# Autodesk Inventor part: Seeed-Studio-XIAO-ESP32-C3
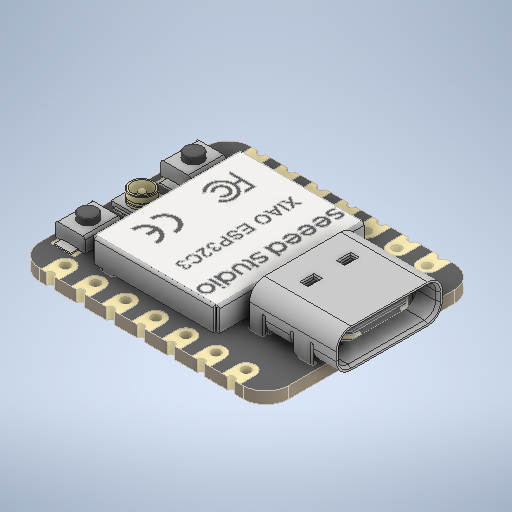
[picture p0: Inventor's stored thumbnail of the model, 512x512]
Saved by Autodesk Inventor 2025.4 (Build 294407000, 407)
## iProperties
Created: 2025-02
Part Number: Seeed-Studio-XIAO-ESP32-C3
Material: Generic
Document SubType Name: Modeling
Designer: Marcio Valenzuela
Density: 1 g/cm^3
Appearance: Default
Sending System: Autodesk Translation Framework v13.20.0.188
Preprocessor: ST-DEVELOPER v20
Title: Seeed-Studio-XIAO-ESP32-C3.step
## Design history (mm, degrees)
feature "BOSS-EXTRUDE14_8__1:1" [Body]
feature "BOSS-EXTRUDE7_4__1:1" [Body]
feature "BOSS-EXTRUDE7_3__1:1" [Body]
feature "BOSS-EXTRUDE14_4__1:1" [Body]
feature "BOSS-EXTRUDE14_2__1:1" [Body]
feature "BOSS-EXTRUDE14_11__1:1" [Body]
feature "BOSS-EXTRUDE7_7__1:1" [Body]
feature "BOSS-EXTRUDE14_9__1:1" [Body]
feature "BOSS-EXTRUDE14_3__1:1" [Body]
feature "BOSS-EXTRUDE14_7__1:1" [Body]
feature "MIRROR2_1:1" [Body]
feature "BOSS-EXTRUDE14_5__1:1" [Body]
feature "BOSS-EXTRUDE14_12__1:1" [Body]
feature "BOSS-EXTRUDE7_8__1:1" [Body]
feature "BOSS-EXTRUDE7_1__1:1" [Body]
feature "BOSS-EXTRUDE14_10__1:1" [Body]
feature "BOSS-EXTRUDE7_9__1:1" [Body]
feature "BOSS-EXTRUDE14_6__1:1" [Body]
feature "CHAMFER9_1:1" [Body]
feature "BOSS-EXTRUDE14_1__1:1" [Body]
feature "BOSS-EXTRUDE7_6__1:1" [Body]
feature "BOSS-EXTRUDE7_2__1:1" [Body]
feature "CUT-EXTRUDE5_1:1" [Body]
feature "BOSS-EXTRUDE7_5__1:1" [Body]
feature "U.FL Connector v1_1:1" [Body]
feature "U.FL Connector v1_1:2" [Body]
feature "U.FL Connector v1_1:3" [Body]
feature "Button (1)_1:1" [Body]
feature "Shield_1:1" [Body]
feature "Button (1)_2:1" [Body]
feature "Body1"
feature "Body2"
body "Solid1"
body "Solid2"
body "Solid3"
body "Solid4"
body "Solid5"
body "Solid6"
body "Solid7"
body "Solid8"
body "Solid9"
body "Solid10"
body "Solid11"
body "Solid12"
body "Solid13"
body "Solid14"
body "Solid15"
body "Solid16"
body "Solid17"
body "Solid18"
body "Solid19"
body "Solid20"
body "Solid21"
body "Solid22"
body "Solid23"
body "Solid24"
body "Solid25"
body "Solid26"
body "Solid27"
body "Solid28"
body "Solid29"
body "Solid30"
body "Solid31"
body "Solid32"
